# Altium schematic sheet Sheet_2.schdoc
size 769 x 209 mm
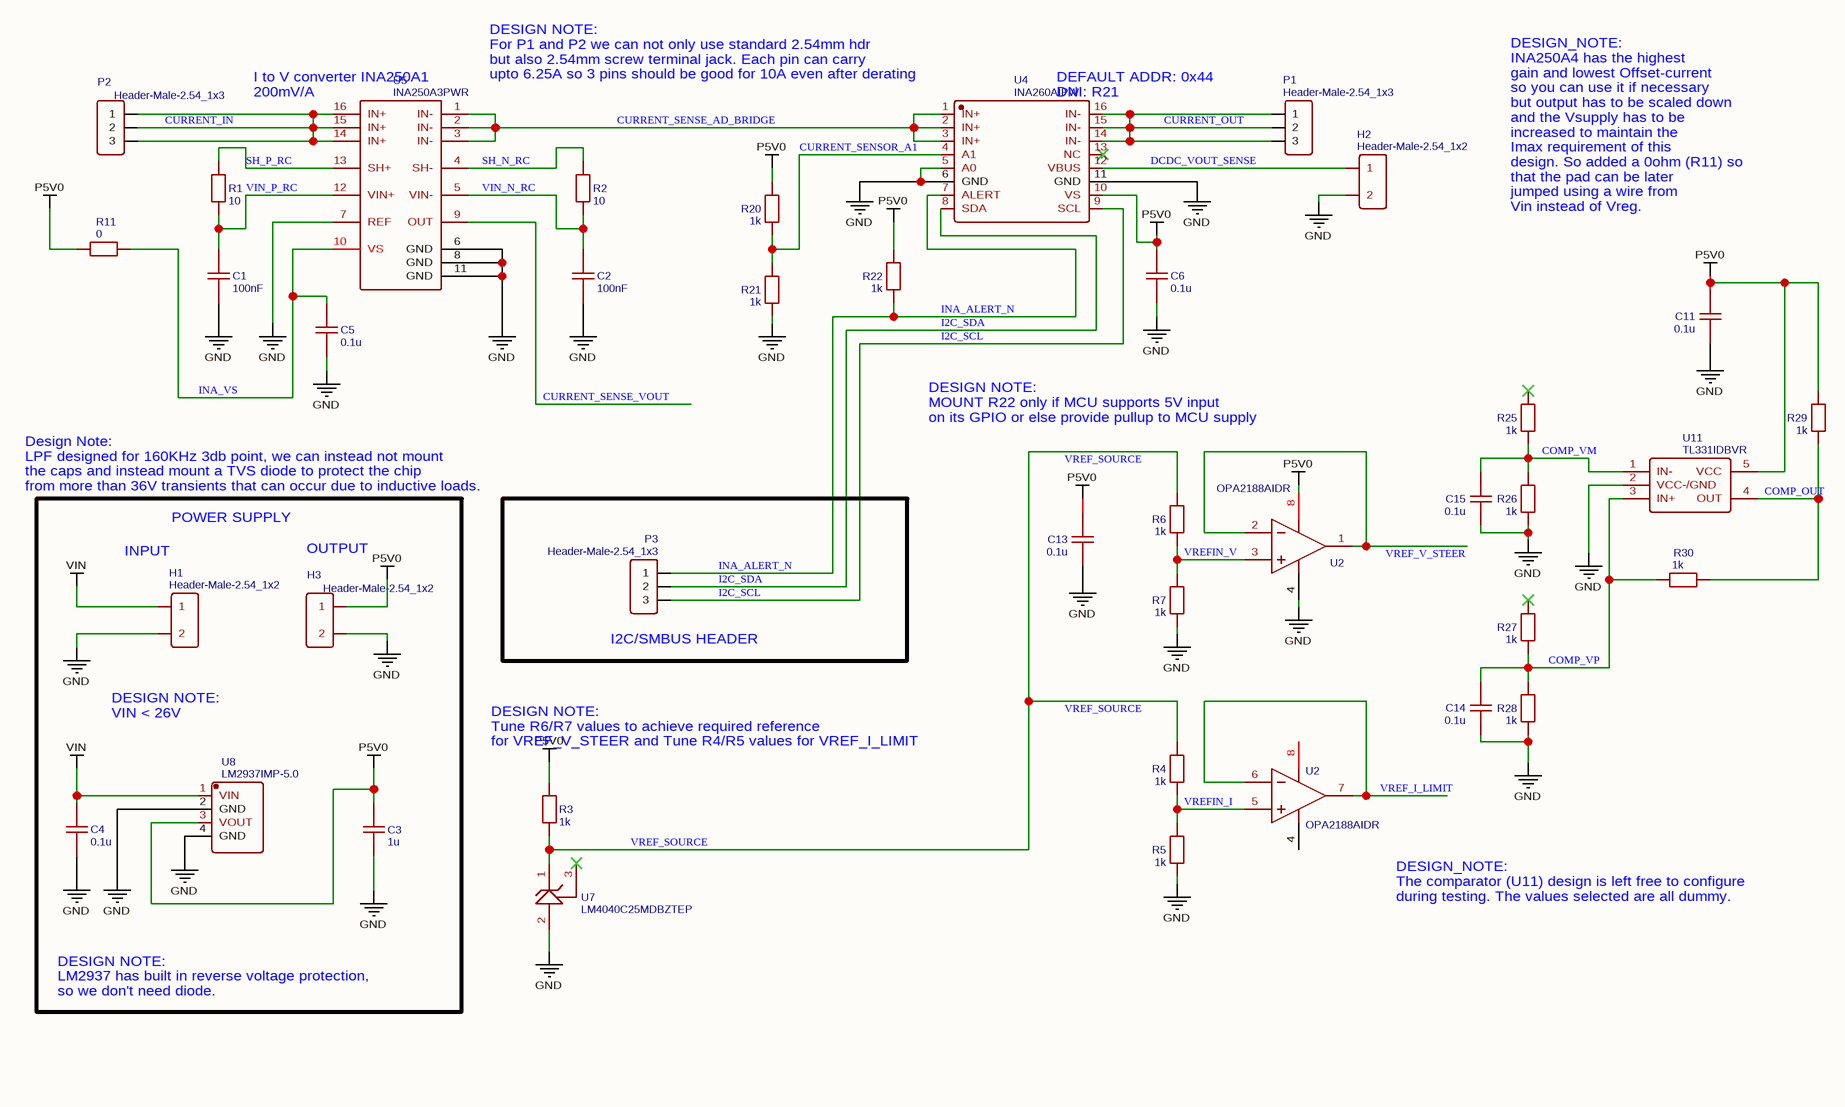
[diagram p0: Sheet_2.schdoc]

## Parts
(Parts that share a designator on the sheet are numbered #1, #2 ... from top to bottom, then left to right.)
C1  100nF  [0402]
C2  100nF  [0402]
C3  1u  [0805]
C4  0.1u  [0805]
C5  0.1u  [0805]
C6  0.1u  [0805]
C11  0.1u  [0805]
C13  0.1u  [0805]
C14  0.1u  [0805]
C15  0.1u  [0805]
H1  Header-Male-2.54_1x2  [HDR-2X1/2.54]
H2  Header-Male-2.54_1x2  [HDR-2X1/2.54]
H3  Header-Male-2.54_1x2  [HDR-2X1/2.54]
P1  Header-Male-2.54_1x3  [HDR-3X1/2.54]
P2  Header-Male-2.54_1x3  [HDR-3X1/2.54]
P3  Header-Male-2.54_1x3  [HDR-3X1/2.54]
R1  10  [0402]
R2  10  [0402]
R3  1k  [0805]
R4  1k  [0805]
R5  1k  [0805]
R6  1k  [0805]
R7  1k  [0805]
R11  0  [0805]
R20  1k  [0805]
R21  1k  [0805]
R22  1k  [0805]
R25  1k  [0805]
R26  1k  [0805]
R27  1k  [0805]
R28  1k  [0805]
R29  1k  [0805]
R30  1k  [0805]
U2#1  OPA2188AIDR  [SOIC-8_150MIL]
U2#2  OPA2188AIDR  [SOIC-8_150MIL]
U4  INA260AIPW  [TSSOP-16]
U5  INA250A3PWR  [TSSOP-16]
U7  LM4040C25MDBZTEP  [SOT23-3]
U8  LM2937IMP-5.0  [SOT-223]
U11  TL331IDBVR  [SOT-23-5]

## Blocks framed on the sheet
I2C/SMBUS HEADER: P3

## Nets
GND: C1.1 C2.1 C3.1 C4.1 C5.1 C6.1 C11.1 C13.1 C14.1 C15.1 H1.2 H2.2 H3.2 R5.1 R7.1 R21.1 R26.1 R28.1 U2#1.4(V-) U4.5(A0) U4.6(GND) U4.11(GND) U5.6(GND) U5.7(REF) U5.8(GND) U5.11(GND) U7.2(ANODE) U8.2(GND) U8.4(GND) U11.2(VCC-/GND)
P5V0: C3.2 C6.2 C11.2 C13.2 H3.1 R3.2 R11.1 R20.2 R22.2 R29.2 U2#1.8(V+) U4.10(VS) U8.3(VOUT) U11.5(VCC)
VIN: C4.2 H1.1 U8.1(VIN)
COMP_OUT: R29.1 R30.1 U11.4(OUT)
COMP_VM: C15.2 R25.1 R26.2 U11.1(IN-)
COMP_VP: C14.2 R27.1 R28.2 R30.2 U11.3(IN+)
CURRENT_IN: P2.1 P2.2 P2.3 U5.14(IN+) U5.15(IN+) U5.16(IN+)
CURRENT_OUT: P1.1 P1.2 P1.3 U4.14(IN-) U4.15(IN-) U4.16(IN-)
CURRENT_SENSE_AD_BRIDGE: U4.1(IN+) U4.2(IN+) U4.3(IN+) U5.1(IN-) U5.2(IN-) U5.3(IN-)
CURRENT_SENSE_VOUT: U5.9(OUT)
CURRENT_SENSOR_A1: R20.1 R21.2 U4.4(A1)
DCDC_VOUT_SENSE: H2.1 U4.12(VBUS)
I2C_SCL: P3.3 U4.9(SCL)
I2C_SDA: P3.2 U4.8(SDA)
INA_ALERT_N: P3.1 R22.1 U4.7(ALERT)
INA_VS: C5.2 R11.2 U5.10(VS)
SH_N_RC: R2.2 U5.4(SH-)
SH_P_RC: R1.2 U5.13(SH+)
VIN_N_RC: C2.2 R2.1 U5.5(VIN-)
VIN_P_RC: C1.2 R1.1 U5.12(VIN+)
VREF_I_LIMIT: U2#2.6(IN_B-) U2#2.7(OUT_B)
VREF_SOURCE: R3.1 R4.2 R6.2 U7.1(CATHODE)
VREF_V_STEER: U2#1.1(OUT_A) U2#1.2(IN_A-)
VREFIN_I: R4.1 R5.2 U2#2.5(IN_B+)
VREFIN_V: R6.1 R7.2 U2#1.3(IN_A+)

Not connected (* = marked no-connect by the designer): R25 2*; R27 2*; U2#2 4(V-) 8(V+); U4 13(NC)*; U7 3(NC)*

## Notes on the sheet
- (near U5) I to V converter INA250A1
  200mV/A
- (near R2) DESIGN NOTE:
  For P1 and P2 we can not only use standard 2.54mm hdr
  but also 2.54mm screw terminal jack. Each pin can carry
  upto 6.25A so 3 pins should be good for 10A even after derating
- (near U4) DEFAULT ADDR: 0x44
  DNI: R21
- DESIGN_NOTE:
  INA250A4 has the highest
  gain and lowest Offset-current
  so you can use it if necessary
  but output has to be scaled down
  and the Vsupply has to be
  increased to maintain the
  Imax requirement of this
  design. So added a 0ohm (R11) so
  that the pad can be later
  jumped using a wire from
  Vin instead of Vreg.
- (near C13) DESIGN NOTE:
  MOUNT R22 only if MCU supports 5V input
  on its GPIO or else provide pullup to MCU supply
- (near H1) Design Note:
  LPF designed for 160KHz 3db point, we can instead not mount
  the caps and instead mount a TVS diode to protect the chip
  from more than 36V transients that can occur due to inductive loads.
- POWER SUPPLY
- (near H3) OUTPUT
- (near H1) INPUT
- (near U8) DESIGN NOTE:
  VIN < 26V
- (near R3) DESIGN NOTE:
  Tune R6/R7 values to achieve required reference
  for VREF_V_STEER and Tune R4/R5 values for VREF_I_LIMIT
- DESIGN_NOTE:
  The comparator (U11) design is left free to configure
  during testing. The values selected are all dummy.
- DESIGN NOTE:
  LM2937 has built in reverse voltage protection,
  so we don't need diode.

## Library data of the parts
C1 C2 = 100nF: nameAlias: Value(F)
C3 = 1u: nameAlias: Value(F)
C4-C6 C11 C13-C15 = 0.1u: nameAlias: Value(F)
H1-H3 = Header-Male-2.54_1x2: BOM_Manufacturer: TE Connectivity; BOM_Manufacturer Part: 826629-2
P1-P3 = Header-Male-2.54_1x3: BOM_Manufacturer: BOOMELE; BOM_Manufacturer Part: Header2.54mm 1*3P
R1 R2 = 10: nameAlias: Value(Ω)
R3 R4 R6 R7 R20 R25-R30 = 1k: nameAlias: Value(Ω)
R5 R21 R22 = 1k: nameAlias: Value(Ω); BOM_MOUNT: NO
R11 = 0: nameAlias: Value(Ω)
U2#1 = OPA2188AIDR: BOM_Manufacturer: TI; subpart_no: 1; tags: Precision Operational Amplifier
U2#2 = OPA2188AIDR: BOM_Manufacturer: TI; subpart_no: 2; tags: Precision Operational Amplifier
U4 = INA260AIPW: BOM_Manufacturer: Texas Instruments; Contributor: LCSC
U5 = INA250A3PWR: BOM_Manufacturer: Texas Instruments; Contributor: neutronstriker; SMT Type: Extend
U7 = LM4040C25MDBZTEP: description: Enhanced Product Precision Micropower Shunt Voltage Reference, 0.5% accuracy, 15 ppm  degC, 15 mA, -55 to 125 degC, 3-pin SOT-23 (DBZ), Green (RoHS  no SbBr)
U8 = LM2937IMP-5.0: BOM_Manufacturer: TI
U11 = TL331IDBVR: BOM_Manufacturer: TI; SMT Type: Extend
